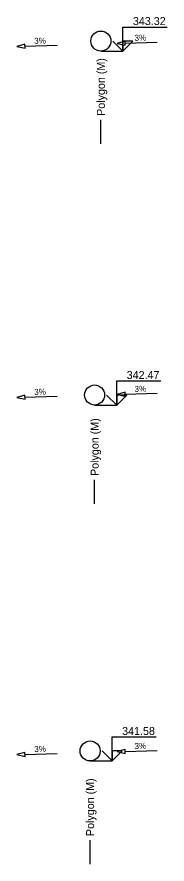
# Model space of a CAD drawing. Extents: x 1989 to 2511, y -2653 to -2294.
# Drawn here: x 2171.48 to 2175.22, y -2325.47 to -2304.3 of the extents above; entities that cross this region are included whole.
import ezdxf

# ---------------------------------------------------------------- set-up
doc = ezdxf.new("R2010")
doc.units = 0
for name, color, linetype in [('KOTA_AUTOMAT', 7, 'Continuous'), ('KRIZENI_AUTOMAT', 7, 'Continuous'), ('POPISY_NAD_TERENEM', 7, 'Continuous'), ('SKLON', 7, 'Continuous')]:
    doc.layers.add(name, color=color, linetype=linetype)

msp = doc.modelspace()

# ---------------------------------------------------------------- linework, layer by layer
at = {"layer": 'KOTA_AUTOMAT'}
for points in [[(2174.121, -2305.154), (2173.871, -2304.904), (2174.121, -2305.154), (2174.121, -2304.554), (2175.221, -2304.554)], [(2174.121, -2305.154), (2174.371, -2304.904), (2174.121, -2304.904), (2174.121, -2305.154)], [(2174.121, -2305.154), (2174.371, -2304.904), (2174.121, -2304.904)], [(2173.571, -2305.154), (2174.121, -2305.154)], [(2173.965, -2314), (2173.715, -2313.75), (2173.965, -2314), (2173.965, -2313.4), (2175.065, -2313.4)], [(2173.965, -2314), (2174.215, -2313.75), (2173.965, -2313.75), (2173.965, -2314)], [(2173.965, -2314), (2174.215, -2313.75), (2173.965, -2313.75)], [(2173.415, -2314), (2173.965, -2314)], [(2173.852, -2322.897), (2173.602, -2322.647), (2173.852, -2322.897), (2173.852, -2322.297), (2174.952, -2322.297)], [(2173.852, -2322.897), (2174.102, -2322.647), (2173.852, -2322.647), (2173.852, -2322.897)], [(2173.852, -2322.897), (2174.102, -2322.647), (2173.852, -2322.647)], [(2173.302, -2322.897), (2173.852, -2322.897)]]:
    msp.add_lwpolyline(points, dxfattribs=at)
at = {"layer": 'KRIZENI_AUTOMAT'}
for centre in [(2173.571, -2304.904), (2173.415, -2313.75), (2173.302, -2322.647)]:
    msp.add_circle(centre, 0.25, dxfattribs=at)
at = {"layer": 'POPISY_NAD_TERENEM'}
for points in [[(2173.571, -2307.473), (2173.571, -2306.873)], [(2173.415, -2316.473), (2173.415, -2315.873)], [(2173.302, -2325.473), (2173.302, -2324.873)]]:
    msp.add_lwpolyline(points, dxfattribs=at)
at = {"layer": 'SKLON'}
for points in [[(2171.676, -2304.982), (2171.477, -2305.038), (2171.679, -2305.082)], [(2174.176, -2304.907), (2173.977, -2304.963), (2174.179, -2305.007)], [(2171.676, -2313.756), (2171.477, -2313.812), (2171.679, -2313.856)], [(2174.176, -2313.681), (2173.977, -2313.737), (2174.179, -2313.781)], [(2171.676, -2322.682), (2171.477, -2322.738), (2171.679, -2322.782)], [(2174.176, -2322.607), (2173.977, -2322.663), (2174.179, -2322.707)]]:
    msp.add_lwpolyline(points, close=True, dxfattribs=at)
for points in [[(2171.679, -2305.082), (2171.676, -2304.982), (2171.477, -2305.038), (2171.679, -2305.082)], [(2171.677, -2305.032), (2172.477, -2305.008)], [(2174.179, -2305.007), (2174.176, -2304.907), (2173.977, -2304.963), (2174.179, -2305.007)], [(2174.177, -2304.957), (2174.977, -2304.933)], [(2171.679, -2313.856), (2171.676, -2313.756), (2171.477, -2313.812), (2171.679, -2313.856)], [(2171.677, -2313.806), (2172.477, -2313.782)], [(2174.179, -2313.781), (2174.176, -2313.681), (2173.977, -2313.737), (2174.179, -2313.781)], [(2174.177, -2313.731), (2174.977, -2313.707)], [(2171.679, -2322.782), (2171.676, -2322.682), (2171.477, -2322.738), (2171.679, -2322.782)], [(2174.179, -2322.707), (2174.176, -2322.607), (2173.977, -2322.663), (2174.179, -2322.707)], [(2174.177, -2322.657), (2174.977, -2322.633)], [(2171.677, -2322.732), (2172.477, -2322.708)]]:
    msp.add_lwpolyline(points, dxfattribs=at)

# ---------------------------------------------------------------- texts
at = {"layer": 'KOTA_AUTOMAT'}
for s, p in [('343.32', (2174.37, -2304.504)), ('342.47', (2174.214, -2313.35)), ('341.58', (2174.101, -2322.247))]:
    msp.add_text(s, height=0.2, dxfattribs=at).set_placement(p)
at = {"layer": 'POPISY_NAD_TERENEM'}
for p in [(2173.671, -2306.773), (2173.515, -2315.773), (2173.402, -2324.773)]:
    msp.add_text('Polygon (M)', height=0.2, rotation=90, dxfattribs=at).set_placement(p)
at = {"layer": 'SKLON'}
for p in [(2171.911, -2304.975), (2174.411, -2304.9), (2174.411, -2313.674), (2171.911, -2313.749), (2174.411, -2322.6), (2171.911, -2322.675)]:
    msp.add_text('3%', height=0.15, rotation=1.7184, dxfattribs=at).set_placement(p)

doc.saveas('drawing.dxf')
